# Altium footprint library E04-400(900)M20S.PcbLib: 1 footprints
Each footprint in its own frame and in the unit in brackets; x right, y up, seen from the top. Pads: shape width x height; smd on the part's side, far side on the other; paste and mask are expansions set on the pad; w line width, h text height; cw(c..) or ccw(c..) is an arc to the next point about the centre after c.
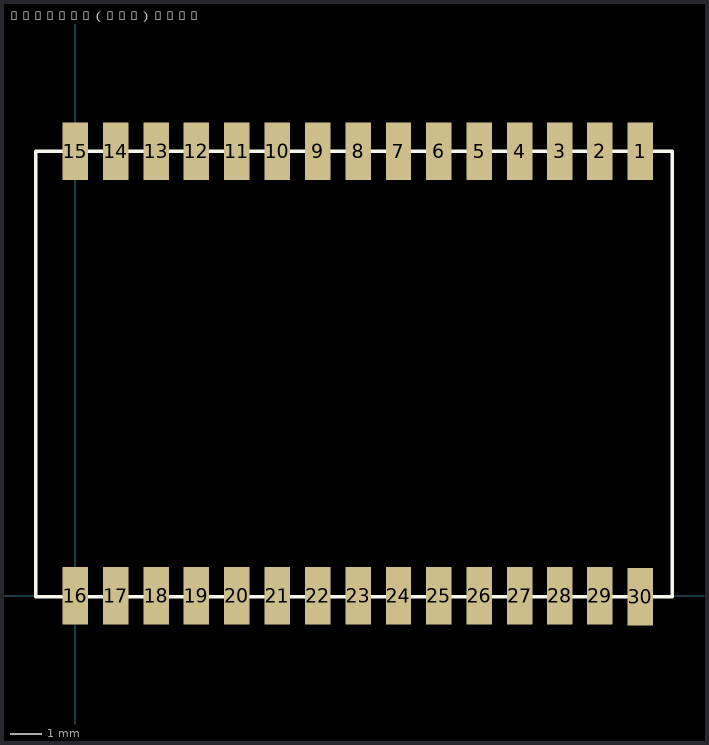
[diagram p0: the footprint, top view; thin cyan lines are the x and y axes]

## E04-400（900）M20S [mm] "20mm*14mm*2.8mm-S"
pads (30):
  rect 0.8x1.8 smd: 1(17.762,13.97) 2(16.492,13.97) 3(15.222,13.97) 4(13.97,13.97) 5(12.7,13.97) 6(11.43,13.97) 7(10.16,13.97) 8(8.89,13.97) 9(7.62,13.97) 10(6.35,13.97) 11(5.08,13.97) 12(3.81,13.97) 13(2.54,13.97) 14(1.27,13.97) 15(0,13.97) 16(0,0) 17(1.27,0) 18(2.54,0) 19(3.81,0) 20(5.08,0) 21(6.35,0) 22(7.62,0) 23(8.89,0) 24(10.16,0) 25(11.43,0) 26(12.7,0) 27(13.97,0) 28(15.222,0) 29(16.492,0) 30(17.762,-0.03)
Top Overlay:
  lines w0.1: -1.238,-0.03 18.762,-0.03 18.762,13.97 -1.238,13.97 -1.238,-0.03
